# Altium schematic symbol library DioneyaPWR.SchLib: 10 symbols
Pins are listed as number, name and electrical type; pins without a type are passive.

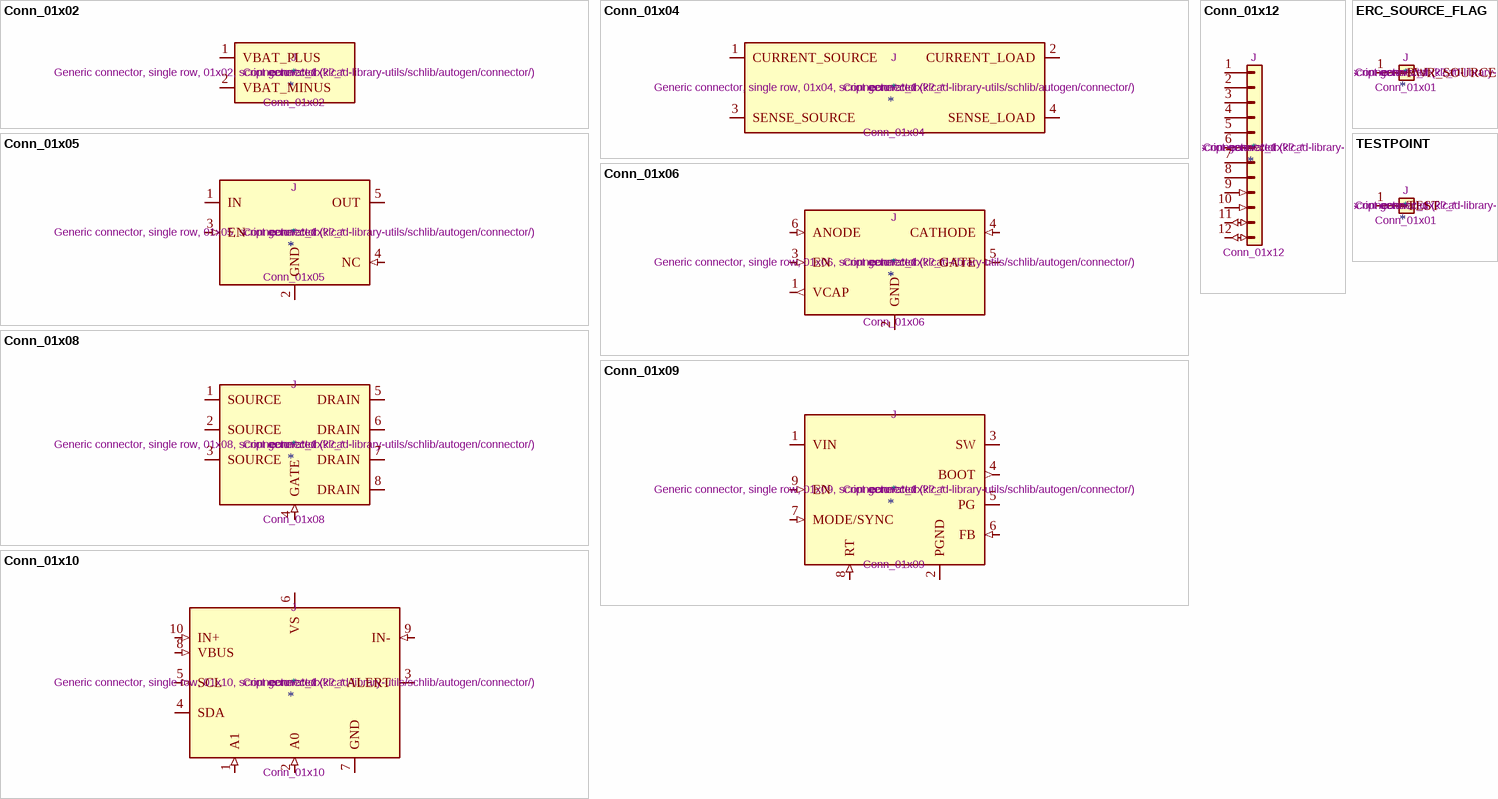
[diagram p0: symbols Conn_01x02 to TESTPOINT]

## Conn_01x02
designator *  value Conn_01x02  Reference: J  Datasheet: ~  ki_keywords: connector  ki_fp_filters: Connector*:*_1x??_*
Generic connector, single row, 01x02, script generated (kicad-library-utils/schlib/autogen/connector/)
pins: 1 VBAT_PLUS, 2 VBAT_MINUS

## Conn_01x04
designator *  value Conn_01x04  Reference: J  Datasheet: ~  ki_keywords: connector  ki_fp_filters: Connector*:*_1x??_*
Generic connector, single row, 01x04, script generated (kicad-library-utils/schlib/autogen/connector/)
pins: 1 CURRENT_SOURCE, 2 CURRENT_LOAD, 3 SENSE_SOURCE, 4 SENSE_LOAD

## Conn_01x05
designator *  value Conn_01x05  Reference: J  Datasheet: ~  ki_keywords: connector  ki_fp_filters: Connector*:*_1x??_*
Generic connector, single row, 01x05, script generated (kicad-library-utils/schlib/autogen/connector/)
pins: 1 IN (power), 2 GND (power), 3 EN (in), 4 NC (in), 5 OUT (power)

## Conn_01x06
designator *  value Conn_01x06  Reference: J  Datasheet: ~  ki_keywords: connector  ki_fp_filters: Connector*:*_1x??_*
Generic connector, single row, 01x06, script generated (kicad-library-utils/schlib/autogen/connector/)
pins: 1 VCAP (out), 2 GND (power), 3 EN (in), 4 CATHODE (in), 5 GATE (out), 6 ANODE (in)

## Conn_01x08
designator *  value Conn_01x08  Reference: J  Datasheet: ~  ki_keywords: connector  ki_fp_filters: Connector*:*_1x??_*
Generic connector, single row, 01x08, script generated (kicad-library-utils/schlib/autogen/connector/)
pins: 1 SOURCE, 2 SOURCE, 3 SOURCE, 4 GATE (in), 5 DRAIN, 6 DRAIN, 7 DRAIN, 8 DRAIN

## Conn_01x09
designator *  value Conn_01x09  Reference: J  Datasheet: ~  ki_keywords: connector  ki_fp_filters: Connector*:*_1x??_*
Generic connector, single row, 01x09, script generated (kicad-library-utils/schlib/autogen/connector/)
pins: 1 VIN (power), 2 PGND (power), 3 SW (power), 4 BOOT (out), 5 PG (oc), 6 FB (in), 7 MODE/SYNC (in), 8 RT (in), 9 EN (in)

## Conn_01x10
designator *  value Conn_01x10  Reference: J  Datasheet: ~  ki_keywords: connector  ki_fp_filters: Connector*:*_1x??_*
Generic connector, single row, 01x10, script generated (kicad-library-utils/schlib/autogen/connector/)
pins: 1 A1 (in), 2 A0 (in), 3 ALERT (oc), 4 SDA (io), 5 SCL (in), 6 VS (power), 7 GND (power), 8 VBUS (in), 9 IN- (in), 10 IN+ (in)

## Conn_01x12
designator *  value Conn_01x12  Reference: J  Datasheet: ~  ki_keywords: connector  ki_fp_filters: Connector*:*_1x??_*
Generic connector, single row, 01x12, script generated (kicad-library-utils/schlib/autogen/connector/)
pins: 1 3V8_MODEM, 2 GND_MODEM, 3 3V3_DIGITAL, 4 GND_DIGITAL, 5 1V8_MIC, 6 GND_MIC, 7 PWR_GOOD (oc), 8 FAULT (oc), 9 EN_MODEM (in), 10 EN_AUX (in), 11 I2C2_SCL (io), 12 I2C2_SDA (io)

## ERC_SOURCE_FLAG
designator *  value Conn_01x01  Reference: J  Datasheet: ~  ki_keywords: connector  ki_fp_filters: Connector*:*_1x??_*
Generic connector, single row, 01x01, script generated (kicad-library-utils/schlib/autogen/connector/)
pins: 1 PWR_SOURCE (power)

## TESTPOINT
designator *  value Conn_01x01  Reference: J  Datasheet: ~  ki_keywords: connector  ki_fp_filters: Connector*:*_1x??_*
Generic connector, single row, 01x01, script generated (kicad-library-utils/schlib/autogen/connector/)
pins: 1 TEST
